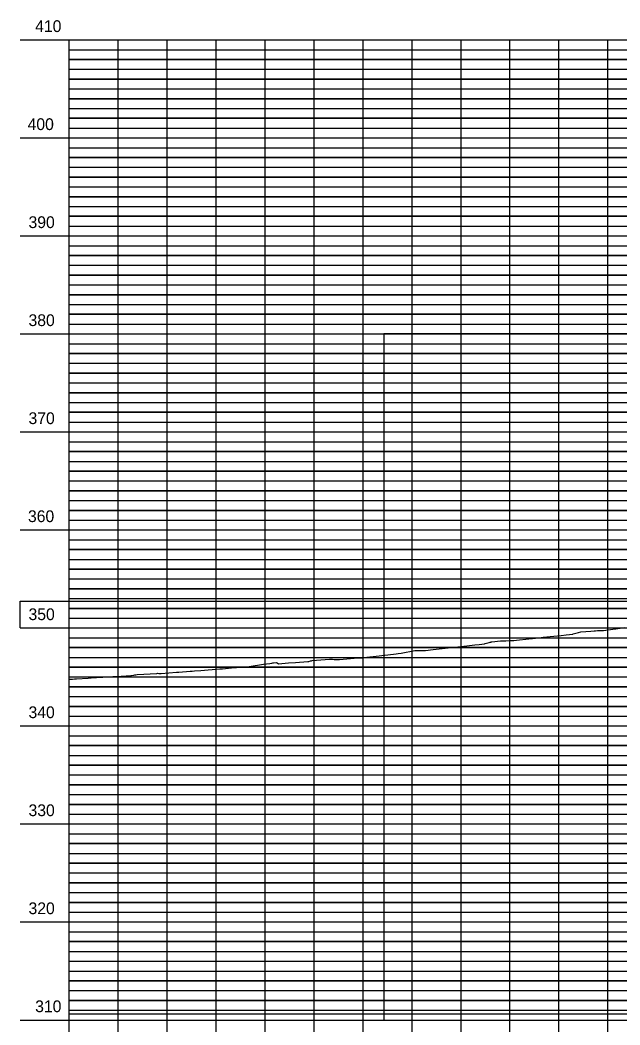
# Model space of a CAD drawing. Extents: x 1195880 to 1289360, y 2059330 to 2086925.
# Drawn here: x 1200369 to 1200675, y 2063848 to 2064360 of the extents above; entities that cross this region are included whole.
import ezdxf

# ---------------------------------------------------------------- set-up
doc = ezdxf.new("R2010")
doc.units = 0
for name, color, linetype in [('Clip', 7, 'Continuous'), ('Default', 7, 'Continuous'), ('Existing Ground PGL', 7, 'Continuous'), ('Grid', 7, 'Continuous'), ('Grid Lables', 7, 'Continuous')]:
    doc.layers.add(name, color=color, linetype=linetype)

msp = doc.modelspace()

# ---------------------------------------------------------------- linework, layer by layer
at = {"layer": 'Clip'}
msp.add_lwpolyline([(1200554.29, 2063850.38), (1201658.61, 2063850.38), (1201658.61, 2064200.38), (1200554.29, 2064200.38)], close=True, dxfattribs=at)
at = {"layer": 'Default'}
for p, q in [((1200368.62, 2064050.38), (1200368.62, 2064063.98)), ((1200368.62, 2064063.98), (1200811.26, 2064063.98))]:
    msp.add_line(p, q, dxfattribs=at)
at = {"layer": 'Existing Ground PGL'}
msp.add_lwpolyline([(1200393.62, 2064024.27), (1200395.35, 2064024.33), (1200396.43, 2064024.4), (1200397.37, 2064024.46), (1200403.44, 2064024.82), (1200404.82, 2064024.9), (1200410.39, 2064025.24), (1200410.6, 2064025.25), (1200410.8, 2064025.27), (1200416.01, 2064025.59), (1200417.85, 2064025.7), (1200425.11, 2064026.16), (1200425.26, 2064026.17), (1200425.42, 2064026.18), (1200426.72, 2064026.37), (1200427.21, 2064026.44), (1200427.7, 2064026.5), (1200428.44, 2064026.61), (1200438.4, 2064027.23), (1200438.68, 2064027.25), (1200439.43, 2064027.2), (1200440.44, 2064027.12), (1200440.45, 2064027.12), (1200440.52, 2064027.12), (1200440.6, 2064027.13), (1200448.38, 2064027.77), (1200449.6, 2064027.87), (1200455.48, 2064028.33), (1200456.44, 2064028.4), (1200457.57, 2064028.48), (1200460.79, 2064028.72), (1200464.67, 2064029.02), (1200470.5, 2064029.46), (1200471.99, 2064029.59), (1200476.55, 2064029.99), (1200481.71, 2064030.42), (1200483.18, 2064030.55), (1200485.52, 2064030.75), (1200492.83, 2064031.85), (1200494.38, 2064032.08), (1200496, 2064032.32), (1200497.09, 2064032.49), (1200497.64, 2064032.57), (1200497.97, 2064032.62), (1200499.44, 2064032.75), (1200499.48, 2064032.73), (1200499.55, 2064032.68), (1200499.73, 2064032.59), (1200500.53, 2064032.15), (1200505.57, 2064032.52), (1200509.12, 2064032.78), (1200515.54, 2064033.26), (1200515.91, 2064033.35), (1200516.75, 2064033.54), (1200516.77, 2064033.55), (1200517.33, 2064033.68), (1200517.75, 2064033.8), (1200526.46, 2064034.43), (1200527.47, 2064034.4), (1200527.96, 2064034.38), (1200528.87, 2064034.35), (1200530.55, 2064034.31), (1200530.72, 2064034.32), (1200531.57, 2064034.36), (1200539.16, 2064034.9), (1200543.52, 2064035.21), (1200544.67, 2064035.34), (1200545.55, 2064035.44), (1200550.35, 2064035.99), (1200559.1, 2064037), (1200560.55, 2064037.16), (1200561.55, 2064037.34), (1200563.04, 2064037.6), (1200570.04, 2064038.87), (1200572.74, 2064038.89), (1200573.84, 2064038.91), (1200575.16, 2064038.93), (1200575.55, 2064038.95), (1200579.34, 2064039.35), (1200583.94, 2064039.83), (1200590.27, 2064040.5), (1200590.55, 2064040.53), (1200596.61, 2064041.24), (1200600.66, 2064041.71), (1200602.94, 2064041.98), (1200605.55, 2064042.28), (1200605.89, 2064042.38), (1200607.24, 2064042.75), (1200607.97, 2064042.95), (1200608.44, 2064043.08), (1200608.76, 2064043.16), (1200608.99, 2064043.23), (1200609.27, 2064043.27), (1200613.83, 2064043.77), (1200614.4, 2064043.79), (1200615.21, 2064043.82), (1200615.61, 2064043.84), (1200616.46, 2064043.87), (1200618.63, 2064043.96), (1200620.56, 2064044.03), (1200621.94, 2064044.18), (1200628.28, 2064044.86), (1200630.05, 2064045.05), (1200634.61, 2064045.53), (1200635.58, 2064045.63), (1200640.95, 2064046.21), (1200644.71, 2064046.61), (1200647.28, 2064046.89), (1200650.62, 2064047.25), (1200650.82, 2064047.38), (1200653.61, 2064048.1), (1200654.81, 2064048.4), (1200659.95, 2064048.81), (1200661.53, 2064048.94), (1200662.2, 2064048.98), (1200663.29, 2064049.01), (1200665.17, 2064049.06), (1200665.68, 2064049.08), (1200666.28, 2064049.15), (1200667.53, 2064049.31), (1200671.02, 2064049.76), (1200672.62, 2064049.96), (1200677.08, 2064050.53)], dxfattribs=at)
at = {"layer": 'Grid'}
for p, q in [((1200368.62, 2064350.38), (1200393.62, 2064350.38)), ((1200368.62, 2064350.38), (1200393.62, 2064350.38)), ((1200393.62, 2063600.38), (1200393.62, 2064350.38)), ((1200393.62, 2064350.38), (1201893.62, 2064350.38)), ((1200393.62, 2064350.38), (1201893.62, 2064350.38)), ((1200418.62, 2063600.38), (1200418.62, 2064350.38)), ((1200443.62, 2063600.38), (1200443.62, 2064350.38)), ((1200468.62, 2063600.38), (1200468.62, 2064350.38)), ((1200493.62, 2063600.38), (1200493.62, 2064350.38)), ((1200518.62, 2063600.38), (1200518.62, 2064350.38)), ((1200543.62, 2063600.38), (1200543.62, 2064350.38)), ((1200568.62, 2063600.38), (1200568.62, 2064350.38)), ((1200593.62, 2063600.38), (1200593.62, 2064350.38)), ((1200618.62, 2063600.38), (1200618.62, 2064350.38)), ((1200643.62, 2063600.38), (1200643.62, 2064350.38)), ((1200668.62, 2063600.38), (1200668.62, 2064350.38)), ((1200393.62, 2064345.38), (1200396.62, 2064345.38)), ((1200393.62, 2064345.38), (1201893.62, 2064345.38)), ((1200393.62, 2064340.38), (1200396.62, 2064340.38)), ((1200393.62, 2064340.38), (1201893.62, 2064340.38)), ((1201893.62, 2064340.38), (1200393.62, 2064340.38)), ((1200393.62, 2064335.38), (1200396.62, 2064335.38)), ((1200393.62, 2064335.38), (1201893.62, 2064335.38)), ((1200393.62, 2064330.38), (1200396.62, 2064330.38)), ((1200393.62, 2064330.38), (1201893.62, 2064330.38)), ((1201893.62, 2064330.38), (1200393.62, 2064330.38)), ((1200393.62, 2064325.38), (1200396.62, 2064325.38)), ((1200393.62, 2064325.38), (1201893.62, 2064325.38)), ((1200393.62, 2064320.38), (1200396.62, 2064320.38)), ((1200393.62, 2064320.38), (1201893.62, 2064320.38)), ((1201893.62, 2064320.38), (1200393.62, 2064320.38)), ((1200393.62, 2064315.38), (1200396.62, 2064315.38)), ((1200393.62, 2064315.38), (1201893.62, 2064315.38)), ((1200393.62, 2064310.38), (1200396.62, 2064310.38)), ((1200393.62, 2064310.38), (1201893.62, 2064310.38)), ((1201893.62, 2064310.38), (1200393.62, 2064310.38)), ((1200393.62, 2064305.38), (1200396.62, 2064305.38)), ((1200393.62, 2064305.38), (1201893.62, 2064305.38)), ((1200368.62, 2064300.38), (1200393.62, 2064300.38)), ((1200393.62, 2064300.38), (1201893.62, 2064300.38)), ((1200393.62, 2064295.38), (1200396.62, 2064295.38)), ((1200393.62, 2064295.38), (1201893.62, 2064295.38)), ((1200393.62, 2064290.38), (1200396.62, 2064290.38)), ((1200393.62, 2064290.38), (1201893.62, 2064290.38)), ((1201893.62, 2064290.38), (1200393.62, 2064290.38)), ((1200393.62, 2064285.38), (1200396.62, 2064285.38)), ((1200393.62, 2064285.38), (1201893.62, 2064285.38)), ((1200393.62, 2064280.38), (1200396.62, 2064280.38)), ((1200393.62, 2064280.38), (1201893.62, 2064280.38)), ((1201893.62, 2064280.38), (1200393.62, 2064280.38)), ((1200393.62, 2064275.38), (1200396.62, 2064275.38)), ((1200393.62, 2064275.38), (1201893.62, 2064275.38)), ((1200393.62, 2064270.38), (1200396.62, 2064270.38)), ((1200393.62, 2064270.38), (1201893.62, 2064270.38)), ((1201893.62, 2064270.38), (1200393.62, 2064270.38)), ((1200393.62, 2064265.38), (1200396.62, 2064265.38)), ((1200393.62, 2064265.38), (1201893.62, 2064265.38)), ((1200393.62, 2064260.38), (1200396.62, 2064260.38)), ((1200393.62, 2064260.38), (1201893.62, 2064260.38)), ((1201893.62, 2064260.38), (1200393.62, 2064260.38)), ((1200393.62, 2064255.38), (1200396.62, 2064255.38)), ((1200393.62, 2064255.38), (1201893.62, 2064255.38)), ((1200368.62, 2064250.38), (1200393.62, 2064250.38)), ((1200393.62, 2064250.38), (1201893.62, 2064250.38)), ((1200393.62, 2064245.38), (1200396.62, 2064245.38)), ((1200393.62, 2064245.38), (1201893.62, 2064245.38)), ((1200393.62, 2064240.38), (1200396.62, 2064240.38)), ((1200393.62, 2064240.38), (1201893.62, 2064240.38)), ((1201893.62, 2064240.38), (1200393.62, 2064240.38)), ((1200393.62, 2064235.38), (1200396.62, 2064235.38)), ((1200393.62, 2064235.38), (1201893.62, 2064235.38)), ((1200393.62, 2064230.38), (1200396.62, 2064230.38)), ((1200393.62, 2064230.38), (1201893.62, 2064230.38)), ((1201893.62, 2064230.38), (1200393.62, 2064230.38)), ((1200393.62, 2064225.38), (1200396.62, 2064225.38)), ((1200393.62, 2064225.38), (1201893.62, 2064225.38)), ((1200393.62, 2064220.38), (1200396.62, 2064220.38)), ((1200393.62, 2064220.38), (1201893.62, 2064220.38)), ((1201893.62, 2064220.38), (1200393.62, 2064220.38)), ((1200393.62, 2064215.38), (1200396.62, 2064215.38)), ((1200393.62, 2064215.38), (1201893.62, 2064215.38)), ((1200393.62, 2064210.38), (1200396.62, 2064210.38)), ((1200393.62, 2064210.38), (1201893.62, 2064210.38)), ((1201893.62, 2064210.38), (1200393.62, 2064210.38)), ((1200393.62, 2064205.38), (1200396.62, 2064205.38)), ((1200393.62, 2064205.38), (1201893.62, 2064205.38)), ((1200368.62, 2064200.38), (1200393.62, 2064200.38)), ((1200393.62, 2064200.38), (1201893.62, 2064200.38)), ((1200393.62, 2064195.38), (1200396.62, 2064195.38)), ((1200393.62, 2064195.38), (1201893.62, 2064195.38)), ((1200393.62, 2064190.38), (1200396.62, 2064190.38)), ((1200393.62, 2064190.38), (1201893.62, 2064190.38)), ((1201893.62, 2064190.38), (1200393.62, 2064190.38)), ((1200393.62, 2064185.38), (1200396.62, 2064185.38)), ((1200393.62, 2064185.38), (1201893.62, 2064185.38)), ((1200393.62, 2064180.38), (1200396.62, 2064180.38)), ((1200393.62, 2064180.38), (1201893.62, 2064180.38)), ((1201893.62, 2064180.38), (1200393.62, 2064180.38)), ((1200393.62, 2064175.38), (1200396.62, 2064175.38)), ((1200393.62, 2064175.38), (1201893.62, 2064175.38)), ((1200393.62, 2064170.38), (1200396.62, 2064170.38)), ((1200393.62, 2064170.38), (1201893.62, 2064170.38)), ((1201893.62, 2064170.38), (1200393.62, 2064170.38)), ((1200393.62, 2064165.38), (1200396.62, 2064165.38)), ((1200393.62, 2064165.38), (1201893.62, 2064165.38)), ((1200393.62, 2064160.38), (1200396.62, 2064160.38)), ((1200393.62, 2064160.38), (1201893.62, 2064160.38)), ((1201893.62, 2064160.38), (1200393.62, 2064160.38)), ((1200393.62, 2064155.38), (1200396.62, 2064155.38)), ((1200393.62, 2064155.38), (1201893.62, 2064155.38)), ((1200368.62, 2064150.38), (1200393.62, 2064150.38)), ((1200393.62, 2064150.38), (1201893.62, 2064150.38)), ((1200393.62, 2064145.38), (1200396.62, 2064145.38)), ((1200393.62, 2064145.38), (1201893.62, 2064145.38)), ((1200393.62, 2064140.38), (1200396.62, 2064140.38)), ((1200393.62, 2064140.38), (1201893.62, 2064140.38)), ((1201893.62, 2064140.38), (1200393.62, 2064140.38)), ((1200393.62, 2064135.38), (1200396.62, 2064135.38)), ((1200393.62, 2064135.38), (1201893.62, 2064135.38)), ((1200393.62, 2064130.38), (1200396.62, 2064130.38)), ((1200393.62, 2064130.38), (1201893.62, 2064130.38)), ((1201893.62, 2064130.38), (1200393.62, 2064130.38)), ((1200393.62, 2064125.38), (1200396.62, 2064125.38)), ((1200393.62, 2064125.38), (1201893.62, 2064125.38)), ((1200393.62, 2064120.38), (1200396.62, 2064120.38)), ((1200393.62, 2064120.38), (1201893.62, 2064120.38)), ((1201893.62, 2064120.38), (1200393.62, 2064120.38)), ((1200393.62, 2064115.38), (1200396.62, 2064115.38)), ((1200393.62, 2064115.38), (1201893.62, 2064115.38)), ((1200393.62, 2064110.38), (1200396.62, 2064110.38)), ((1200393.62, 2064110.38), (1201893.62, 2064110.38)), ((1201893.62, 2064110.38), (1200393.62, 2064110.38)), ((1200393.62, 2064105.38), (1200396.62, 2064105.38)), ((1200393.62, 2064105.38), (1201893.62, 2064105.38)), ((1200368.62, 2064100.38), (1200393.62, 2064100.38)), ((1200393.62, 2064100.38), (1201893.62, 2064100.38)), ((1200393.62, 2064095.38), (1200396.62, 2064095.38)), ((1200393.62, 2064095.38), (1201893.62, 2064095.38)), ((1200393.62, 2064090.38), (1200396.62, 2064090.38)), ((1200393.62, 2064090.38), (1201893.62, 2064090.38)), ((1201893.62, 2064090.38), (1200393.62, 2064090.38)), ((1200393.62, 2064085.38), (1200396.62, 2064085.38)), ((1200393.62, 2064085.38), (1201893.62, 2064085.38)), ((1200393.62, 2064080.38), (1200396.62, 2064080.38)), ((1200393.62, 2064080.38), (1201893.62, 2064080.38)), ((1201893.62, 2064080.38), (1200393.62, 2064080.38)), ((1200393.62, 2064075.38), (1200396.62, 2064075.38)), ((1200393.62, 2064075.38), (1201893.62, 2064075.38)), ((1200393.62, 2064070.38), (1200396.62, 2064070.38)), ((1200393.62, 2064070.38), (1201893.62, 2064070.38)), ((1201893.62, 2064070.38), (1200393.62, 2064070.38)), ((1200393.62, 2064065.38), (1200396.62, 2064065.38)), ((1200393.62, 2064065.38), (1201893.62, 2064065.38)), ((1200393.62, 2064060.38), (1200396.62, 2064060.38)), ((1200393.62, 2064060.38), (1201893.62, 2064060.38)), ((1201893.62, 2064060.38), (1200393.62, 2064060.38)), ((1200393.62, 2064055.38), (1200396.62, 2064055.38)), ((1200393.62, 2064055.38), (1201893.62, 2064055.38)), ((1200368.62, 2064050.38), (1200393.62, 2064050.38)), ((1200393.62, 2064050.38), (1201893.62, 2064050.38)), ((1200393.62, 2064045.38), (1200396.62, 2064045.38)), ((1200393.62, 2064045.38), (1201893.62, 2064045.38)), ((1200393.62, 2064040.38), (1200396.62, 2064040.38)), ((1200393.62, 2064040.38), (1201893.62, 2064040.38)), ((1201893.62, 2064040.38), (1200393.62, 2064040.38)), ((1200393.62, 2064035.38), (1200396.62, 2064035.38)), ((1200393.62, 2064035.38), (1201893.62, 2064035.38)), ((1200393.62, 2064030.38), (1200396.62, 2064030.38)), ((1200393.62, 2064030.38), (1201893.62, 2064030.38)), ((1201893.62, 2064030.38), (1200393.62, 2064030.38)), ((1200393.62, 2064025.38), (1200396.62, 2064025.38)), ((1200393.62, 2064025.38), (1201893.62, 2064025.38)), ((1200393.62, 2064020.38), (1200396.62, 2064020.38)), ((1200393.62, 2064020.38), (1201893.62, 2064020.38)), ((1201893.62, 2064020.38), (1200393.62, 2064020.38)), ((1200393.62, 2064015.38), (1200396.62, 2064015.38)), ((1200393.62, 2064015.38), (1201893.62, 2064015.38)), ((1200393.62, 2064010.38), (1200396.62, 2064010.38)), ((1200393.62, 2064010.38), (1201893.62, 2064010.38)), ((1201893.62, 2064010.38), (1200393.62, 2064010.38)), ((1200393.62, 2064005.38), (1200396.62, 2064005.38)), ((1200393.62, 2064005.38), (1201893.62, 2064005.38)), ((1200368.62, 2064000.38), (1200393.62, 2064000.38)), ((1200393.62, 2064000.38), (1201893.62, 2064000.38)), ((1200393.62, 2063995.38), (1200396.62, 2063995.38)), ((1200393.62, 2063995.38), (1201893.62, 2063995.38)), ((1200393.62, 2063990.38), (1200396.62, 2063990.38)), ((1200393.62, 2063990.38), (1201893.62, 2063990.38)), ((1201893.62, 2063990.38), (1200393.62, 2063990.38)), ((1200393.62, 2063985.38), (1200396.62, 2063985.38)), ((1200393.62, 2063985.38), (1201893.62, 2063985.38)), ((1201893.62, 2063980.44), (1200393.62, 2063980.44)), ((1200393.62, 2063980.38), (1200396.62, 2063980.38)), ((1200393.62, 2063980.38), (1201893.62, 2063980.38)), ((1201893.62, 2063980.38), (1200393.62, 2063980.38)), ((1200393.62, 2063975.38), (1200396.62, 2063975.38)), ((1200393.62, 2063975.38), (1201893.62, 2063975.38)), ((1200393.62, 2063970.38), (1200396.62, 2063970.38)), ((1200393.62, 2063970.38), (1201893.62, 2063970.38)), ((1201893.62, 2063970.38), (1200393.62, 2063970.38)), ((1200393.62, 2063965.38), (1200396.62, 2063965.38)), ((1200393.62, 2063965.38), (1201893.62, 2063965.38)), ((1200393.62, 2063960.38), (1200396.62, 2063960.38)), ((1200393.62, 2063960.38), (1201893.62, 2063960.38)), ((1201893.62, 2063960.38), (1200393.62, 2063960.38)), ((1200393.62, 2063955.38), (1200396.62, 2063955.38)), ((1200393.62, 2063955.38), (1201893.62, 2063955.38)), ((1200368.62, 2063950.38), (1200393.62, 2063950.38)), ((1200393.62, 2063950.38), (1201893.62, 2063950.38)), ((1200393.62, 2063945.38), (1200396.62, 2063945.38)), ((1200393.62, 2063945.38), (1201893.62, 2063945.38)), ((1200393.62, 2063940.38), (1200396.62, 2063940.38)), ((1200393.62, 2063940.38), (1201893.62, 2063940.38)), ((1201893.62, 2063940.38), (1200393.62, 2063940.38)), ((1200393.62, 2063935.38), (1200396.62, 2063935.38)), ((1200393.62, 2063935.38), (1201893.62, 2063935.38)), ((1200393.62, 2063930.38), (1200396.62, 2063930.38)), ((1200393.62, 2063930.38), (1201893.62, 2063930.38)), ((1201893.62, 2063930.38), (1200393.62, 2063930.38)), ((1200393.62, 2063925.38), (1200396.62, 2063925.38)), ((1200393.62, 2063925.38), (1201893.62, 2063925.38)), ((1200393.62, 2063920.38), (1200396.62, 2063920.38)), ((1200393.62, 2063920.38), (1201893.62, 2063920.38)), ((1201893.62, 2063920.38), (1200393.62, 2063920.38)), ((1200393.62, 2063915.38), (1200396.62, 2063915.38)), ((1200393.62, 2063915.38), (1201893.62, 2063915.38)), ((1200393.62, 2063910.38), (1200396.62, 2063910.38)), ((1200393.62, 2063910.38), (1201893.62, 2063910.38)), ((1201893.62, 2063910.38), (1200393.62, 2063910.38)), ((1200368.62, 2063900.38), (1200393.62, 2063900.38)), ((1200393.62, 2063905.38), (1200396.62, 2063905.38)), ((1200393.62, 2063905.38), (1201893.62, 2063905.38)), ((1200393.62, 2063900.38), (1201893.62, 2063900.38)), ((1200393.62, 2063895.38), (1200396.62, 2063895.38)), ((1200393.62, 2063895.38), (1201893.62, 2063895.38)), ((1200393.62, 2063890.38), (1200396.62, 2063890.38)), ((1200393.62, 2063890.38), (1201893.62, 2063890.38)), ((1201893.62, 2063890.38), (1200393.62, 2063890.38)), ((1200393.62, 2063885.38), (1200396.62, 2063885.38)), ((1200393.62, 2063885.38), (1201893.62, 2063885.38)), ((1200393.62, 2063880.38), (1200396.62, 2063880.38)), ((1200393.62, 2063880.38), (1201893.62, 2063880.38)), ((1200393.62, 2063875.38), (1200396.62, 2063875.38)), ((1200393.62, 2063875.38), (1201893.62, 2063875.38)), ((1200393.62, 2063870.38), (1200396.62, 2063870.38)), ((1200393.62, 2063870.38), (1201893.62, 2063870.38)), ((1201893.62, 2063870.38), (1200393.62, 2063870.38)), ((1200393.62, 2063865.38), (1200396.62, 2063865.38)), ((1200393.62, 2063865.38), (1201893.62, 2063865.38)), ((1200393.62, 2063860.38), (1200396.62, 2063860.38)), ((1200393.62, 2063860.38), (1201893.62, 2063860.38)), ((1201893.62, 2063860.38), (1200393.62, 2063860.38)), ((1200393.62, 2063855.38), (1200396.62, 2063855.38)), ((1200393.62, 2063855.38), (1201893.62, 2063855.38)), ((1200368.62, 2063850.38), (1200393.62, 2063850.38)), ((1200393.62, 2063853.5), (1201893.62, 2063853.5)), ((1200393.62, 2063850.38), (1201893.62, 2063850.38))]:
    msp.add_line(p, q, dxfattribs=at)

# ---------------------------------------------------------------- texts
at = {"layer": 'Grid Lables'}
for s, p in [('410', (1200376.33, 2064354.38)), ('410', (1200376.33, 2064354.38)), ('400', (1200372.46, 2064304.38)), ('390', (1200372.93, 2064254.38)), ('380', (1200372.93, 2064204.38)), ('370', (1200372.93, 2064154.38)), ('360', (1200372.65, 2064104.38)), ('350', (1200372.93, 2064054.38)), ('340', (1200372.93, 2064004.38)), ('330', (1200372.93, 2063954.38)), ('320', (1200372.93, 2063904.38)), ('310', (1200376.33, 2063854.38))]:
    msp.add_text(s, height=6, dxfattribs=at).set_placement(p)

doc.saveas('drawing.dxf')
